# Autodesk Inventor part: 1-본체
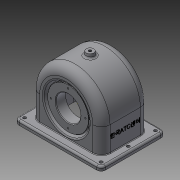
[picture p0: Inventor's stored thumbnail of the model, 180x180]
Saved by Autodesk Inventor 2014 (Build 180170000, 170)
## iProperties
Created: 2015-09
Part Number: 1-본체
Material: 일반
Document SubType Name: Modeling
Designer: Administrator
Density: 1 g/cm^3
Appearance: 기본값
Author: Administrator
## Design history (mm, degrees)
sketch "스케치2"
  geometry: L1 (57, 0)-(-57, 0); L2 (-57, 0)-(-57, -47); L3 (-57, -47)-(57, -47); L4 (57, -47)-(57, 0); A1 r 57 centre (0, 0) between (32.249, -47) and (-32.249, -47); 2 further points
  constraints: 8 end point, 2 coincident, 2 parallel, 2 point on circle, 2 point on line, 1 centre point, 1 horizontal, 1 midpoint, 1 perpendicular, 1 tangent
  dimensions: "d3" = 57 radius of A1; "d4" = 47 distance of L1.end L2.end
extrude "돌출1" new body sketch "스케치2" stored distance "d5" = 77; taper "d6" = 0 deg
sketch "스케치4"
  geometry: L1 (70, -40)-(-70, -40); L2 (-70, -40)-(-70, -47); L3 (-70, -47)-(70, -47); L4 (70, -47)-(70, -40); L5 (-57, -47)-(57, -47) reference; 2 further points
  constraints: 8 end point, 2 parallel, 1 collinear, 1 horizontal, 1 midpoint, 1 perpendicular, 1 vertical alignment
  dimensions: "d9" = 7 distance of L1.end L2.end; "d10" = 140 distance of L2.end L3.end
extrude "돌출2" join sketch "스케치4" stored distance "d11" = 104; taper "d12" = 0 deg
sketch "스케치6"
  geometry: L1 (121, -85.5)-(19, -85.5); L2 (19, -85.5)-(19, -18.5); L3 (19, -18.5)-(121, -18.5); L4 (121, -18.5)-(121, -85.5); L5 (140, -104)-(140, 0) reference; L6 (0, 0)-(140, 0) reference; L7 (0, -104)-(0, 0) reference; L8 (140, -104)-(0, -104) reference; 5 further points
  constraints: 8 end point, 4 midpoint, 2 parallel, 1 horizontal, 1 horizontal alignment, 1 perpendicular, 1 vertical alignment
  dimensions: "d13" = 102 distance of L2.end L3.end; "d14" = 67 distance of L1.end L2.end
extrude "돌출3" cut sketch "스케치6" stored distance "d15" = 104; taper "d16" = 0 deg
sketch "스케치7"
  geometry: L1 (-33.5, 51)-(33.5, 51); L2 (33.5, 51)-(33.5, 0); L3 (33.5, 0)-(-33.5, 0); L4 (-33.5, 0)-(-33.5, 51); L5 (-38.5, 57)-(38.5, 57) reference; 2 further points
  constraints: 8 end point, 2 parallel, 1 coincident, 1 horizontal, 1 midpoint, 1 perpendicular
  dimensions: "d17" = 67 distance of L1.start L1.end; "d18" = 6 distance between parallel lines of L1 L5
revolve "회전1" sketch "스케치7" stored, may be unused: angle "d19" = 90 deg
sketch "스케치8"
  geometry: C1 r 31 at (0, 0); 1 further point
  constraints: 1 centre point, 1 coincident
  dimensions: "d20" = 62 diameter of C1
extrude "돌출4" join sketch "스케치8" distance "d21" = 10; taper "d22" = 0 deg
node "작업 평면3"
  node "작업 평면2"
sketch "스케치12"
  geometry: 1 further point
sketch "스케치13"
  geometry: C1 r 28 at (0, 0); 1 further point
  constraints: 1 centre point, 1 coincident
  dimensions: "d25" = 56 diameter of C1
extrude "돌출5" join sketch "스케치13" stored distance "d26" = 10; taper "d27" = 40 deg
sketch "스케치15"
  geometry: L1 (-19.5, 28)-(-33.5, 39.747) reference; L2 (-38.5, 57)-(-38.5, 0) reference; L3 (-35.5, 33)-(-33.237, 33); L4 (-35.5, 0)-(-35.5, 33); L5 (-38.5, 0)-(-35.5, 0); L6 (-33.237, 33)-(-38.5, 37.416); 1 further point
  constraints: 8 end point, 1 parallel, 1 perpendicular, 1 point on line, 1 vertical
  dimensions: "d31" = 3 distance between parallel lines of L2 L4; "d88" = 5 distance between parallel lines of L6 L1; "d89" = 66 diameter of L3 L5
revolve "회전2" sketch "스케치15" stored, may be unused: angle "d32" = 90 deg
hole "구멍1" diameter "d36" = 40; stored, may be unused: countersink angle "d40" = 90 deg, drill point angle "d42" = 0 deg; dims "d34" = 10, "d35" = 10, "d37" = 6, "d38" = 4, "d39" = 2, "d41" = 8
hole "구멍2" diameter "d45" = 40; stored, may be unused: countersink angle "d49" = 90 deg, drill point angle "d51" = 0 deg; dims "d43" = 10, "d44" = 10, "d46" = 6, "d47" = 4, "d48" = 2, "d50" = 8
node "작업 평면4"
sketch "스케치17"
  geometry: C1 r 6 at (0, 0); 1 further point
  constraints: 1 centre point, 1 coincident
  dimensions: "d53" = 12 diameter of C1
extrude "돌출6" join sketch "스케치17" stored distance "d54" = 10; taper "d55" = 10 deg
sketch "스케치18"
  geometry: L1 (0, 0)-(0, 28); C1 r 20 at (0, 0) reference; 2 further points
  constraints: 2 end point, 1 coincident, 1 vertical
  dimensions: "d57" = 28 distance of L1.start L1.end
hole "구멍3" sketch "스케치18" at (0, 28) diameter "d58" = 2.459; stored, may be unused: countersink angle "d62" = 90 deg, drill point angle "d64" = 118 deg; dims "d59" = 7, "d60" = 4, "d61" = 2, "d63" = 9
sketch "스케치19"
  geometry: L1 (0, 0)-(0, -24); C1 r 31 at (0, 0) reference; 2 further points
  constraints: 2 end point, 1 coincident, 1 vertical
  dimensions: "d68" = 24 distance of L1.start L1.end
hole "구멍4" sketch "스케치19" at (0, -24) diameter "d69" = 2.459; stored, may be unused: countersink angle "d73" = 90 deg, drill point angle "d75" = 118 deg; dims "d70" = 6, "d71" = 4, "d72" = 2, "d74" = 8
hole "구멍5" diameter "d81" = 4.459; stored, may be unused: countersink angle "d85" = 90 deg, drill point angle "d87" = 0 deg; dims "d82" = 6, "d83" = 4, "d84" = 2, "d86" = 8, "d121" = 10, "d122" = 10
fillet "모깎기2" dims "d90" = 3
sketch "스케치21"
  geometry: L1 (0, 104)-(0, 0) reference; L2 (140, 0)-(0, 0) reference; 2 further points
  dimensions: "d91" = 8 distance from line of L1 point (8, 8); "d92" = 8 distance from line of L2 point (8, 8)
hole "구멍6" sketch "스케치21" at (8, 8) diameter "d93" = 5; stored, may be unused: countersink angle "d97" = 90 deg, drill point angle "d99" = 0 deg; dims "d94" = 6, "d95" = 4, "d96" = 2, "d98" = 8
fillet "모깎기3" dims "d103" = 7
fillet "모깎기5" dims "d105" = 3
fillet "모깎기6" dims "d106" = 3
chamfer "모따기1" distance "d107" = 1; stored, may be unused: second distance "d108" = 2, angle "d109" = 45 deg
fillet "모깎기7" dims "d113" = 9
fillet "모깎기8" dims "d114" = 14
fillet "모깎기9" dims "d115" = 1
fillet "모깎기10" dims "d116" = 0.5
fillet "모깎기11" dims "d117" = 3
sketch "스케치22"
  geometry: L1 (29.508, -7.81)-(29.508, 56.81); L2 (29.508, 56.81)-(4.492, 56.81); L3 (4.492, 56.81)-(4.492, -7.81); L4 (4.492, -7.81)-(29.508, -7.81); L5 (47, -20.5)-(47, 69.5) reference; L6 (0, 0)-(0, 49) reference; 4 further points
  constraints: 3 midpoint, 1 horizontal, 1 horizontal alignment, 2 other
  dimensions: "d118" = 30 distance from line of L5 point (17, -7.81)
feature "엠보싱1" sketch "스케치22" dims "d3" = 57, "d4" = 47, "d119" = 0.5, "d120" = 0
node "솔리드1"
pattern_circular "원형 패턴2" dims angle "d77" = 360 deg
pattern_linear "직사각형 패턴1" dims "d102" = 44
mirror "대칭1"
pattern_circular "원형 패턴3" dims angle "d111" = 360 deg
node "투영된 루프1"
other parameters: "d23" = 0, "d24" = -19, "d29" = 3, "d52" = 63
